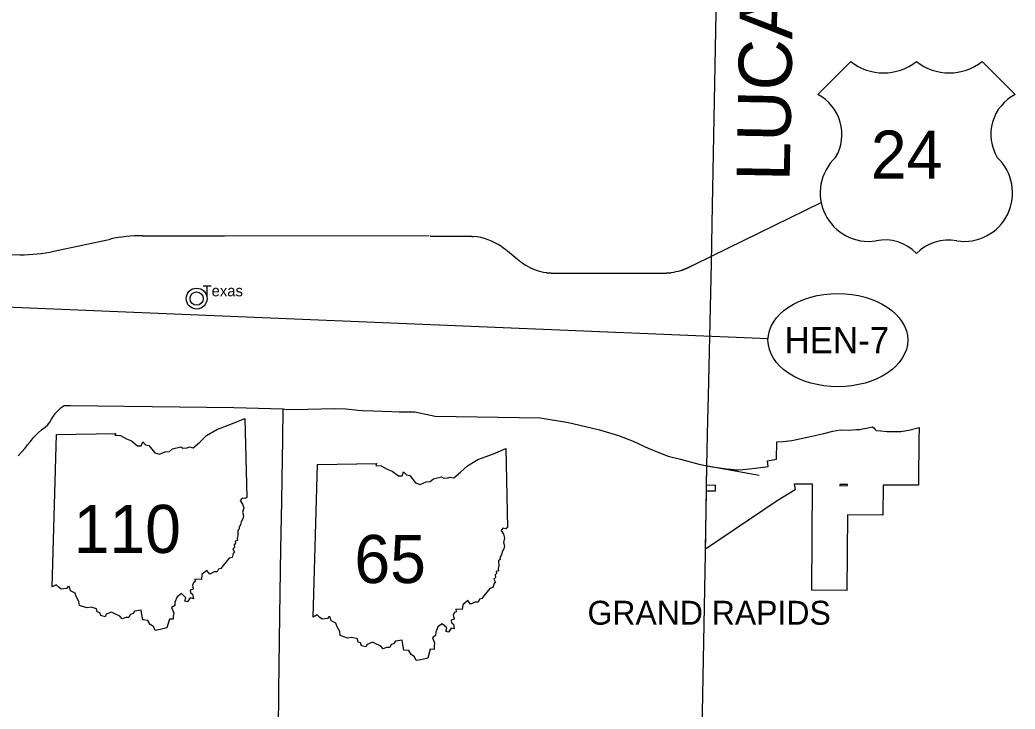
# Model space of a CAD drawing. Extents: x -62 to 810, y 0 to 440.
# Drawn here: x 408.1 to 514.9, y 275.7 to 349.6 of the extents above; entities that cross this region are included whole.
import ezdxf

# ---------------------------------------------------------------- set-up
doc = ezdxf.new("R2010")
doc.units = 0
for name, color, linetype in [('DV_X_Corp_Line', 7, 'Continuous'), ('GM_X_Adjacent_County_Text', 7, 'Continuous'), ('GM_X_Corporation_Text', 7, 'Continuous'), ('GM_X_County', 7, 'Continuous'), ('GM_X_State_Route', 7, 'Continuous'), ('PV_P_Text', 7, 'Continuous'), ('SH_Data', 7, 'Continuous')]:
    doc.layers.add(name, color=color, linetype=linetype)

msp = doc.modelspace()

# ---------------------------------------------------------------- linework, layer by layer
at = {"layer": 'DV_X_Corp_Line'}
for points in [[(481.71, 292.82), (481.82, 299.09), (482.78, 299.07), (482.78, 299.68), (481.83, 299.66), (481.87, 301.77), (482.48, 301.68), (483.97, 301.46), (484.43, 301.4), (484.71, 301.36), (484.94, 301.34), (485.26, 301.34), (485.71, 301.37), (486.42, 301.45), (487.03, 301.52), (488.18, 301.65), (488.45, 301.69), (488.38, 302.29), (489.35, 302.47), (489.37, 304.34), (490.04, 304.39), (490.97, 304.5), (492.79, 304.87), (494.42, 305.24), (495.37, 305.5), (496.18, 305.62), (497.09, 305.61), (497.93, 305.68), (498.27, 305.68), (498.57, 305.75), (498.98, 305.8), (499.6, 305.97), (499.78, 305.85), (499.89, 305.69), (500.03, 305.57), (500.53, 305.51), (501.2, 305.46), (502.03, 305.47), (502.68, 305.44), (503.53, 305.61), (504.63, 305.9), (504.61, 304.59), (504.56, 300.14), (504.56, 299.68), (500.79, 299.69), (500.73, 296.48), (496.94, 296.51), (496.87, 288.38), (493.14, 288.44), (493.2, 299.82), (491.74, 299.81), (491.23, 299.8), (491.3, 299.44), (491.34, 299.19), (489.39, 298.01)], [(496.14, 299.77), (496.14, 299.63), (496.97, 299.65), (496.97, 299.78)]]:
    msp.add_lwpolyline(points, close=True, dxfattribs=at)
for radius in [1.12, 0.71]:
    msp.add_circle((427.1, 319.72), radius, dxfattribs=at)
at = {"layer": 'GM_X_County'}
msp.add_lwpolyline([(480.48, 186.82), (480.48, 201.49), (480.48, 201.72), (480.54, 216.9), (480.6, 231.89), (480.65, 234.56), (480.88, 246.96), (481.15, 262.15), (481.29, 269.58), (481.42, 277.21), (481.7, 292.34), (481.87, 301.77), (481.96, 306.7), (482.02, 309.24), (482.36, 323.53), (482.48, 329.73), (482.51, 331.51), (482.76, 344.73), (482.9, 352.28)], dxfattribs=at)
at = {"layer": 'GM_X_State_Route'}
for p, q in [((482.43, 324.31), (494.13, 330.02)), ((414.8, 325.45), (417.84, 326.1)), ((421.27, 326.47), (428.1, 326.47)), ((428.1, 326.47), (430.08, 326.47)), ((430.08, 326.47), (452.06, 326.48)), ((411.78, 324.8), (414.8, 325.45)), ((403.76, 324.49), (408.13, 324.43)), ((460.85, 324.51), (461.28, 324.16)), ((480.39, 323.31), (482.43, 324.31)), ((466.02, 322.45), (476.64, 322.45)), ((452.7, 307.09), (463.96, 306.91))]:
    msp.add_line(p, q, dxfattribs=at)
for points in [[(411.22, 306.28), (411.35, 306.45), (411.53, 306.77), (411.75, 307.1), (411.96, 307.42), (412.55, 308.02), (412.87, 308.24), (413.02, 308.25), (413.28, 308.23), (413.58, 308.23), (431.09, 308.03)], [(431.09, 308.03), (436.4, 307.87)], [(435.86, 271.19), (435.89, 273.28), (435.94, 277.66), (436.03, 285.69), (436.15, 292.88), (436.23, 297.93), (436.28, 300.39), (436.36, 304.58), (436.4, 307.87)], [(436.4, 307.87), (436.73, 307.8), (438.99, 307.85), (441.94, 307.91), (443.13, 307.89), (444.43, 307.76), (444.91, 307.7), (446.05, 307.68), (448.05, 307.6), (448.83, 307.57), (450.53, 307.56), (452.7, 307.09)], [(463.96, 306.91), (466.79, 306.44), (467.47, 306.32), (470.32, 305.65), (472.39, 305.03), (473.96, 304.41), (475.64, 303.63), (477.71, 302.82), (479.03, 302.47), (481.14, 301.9), (487.46, 300.77)], [(407.94, 302.85), (408.34, 303.27), (408.69, 303.66), (408.95, 304.03), (409.23, 304.34), (409.62, 304.84), (409.87, 305.11), (410.1, 305.32), (410.46, 305.62), (410.85, 305.92), (411.12, 306.16), (411.2, 306.27), (411.22, 306.28)]]:
    msp.add_lwpolyline(points, dxfattribs=at)
for centre, radius, start, end in [((421.28, 310.14), 16.33, 90.0111, 102.1667), ((456.17, 319.89), 6.53, 56.1951, 84.2361), ((408.34, 340.76), 16.33, 269.2957, 282.1667), ((465.31, 327.91), 5.44, 237.9201, 262.5), ((477.35, 327.91), 5.44, 277.5, 288.5)]:
    msp.add_arc(centre, radius, start, end, dxfattribs=at)
for points in [[(452.17, 326.43), (455.51, 326.43), (455.53, 326.43), (455.55, 326.43), (455.57, 326.43), (455.58, 326.43), (455.6, 326.43), (455.62, 326.43), (455.64, 326.43), (455.66, 326.43), (455.67, 326.43), (455.69, 326.43), (455.71, 326.43), (455.73, 326.43), (455.74, 326.43), (455.76, 326.43), (455.78, 326.43), (455.8, 326.43), (455.82, 326.43), (455.83, 326.43), (455.85, 326.43), (455.87, 326.43), (455.89, 326.43), (455.9, 326.43), (455.92, 326.43), (455.94, 326.43), (455.96, 326.43), (455.98, 326.43), (455.99, 326.43), (456.01, 326.43), (456.03, 326.43), (456.05, 326.43), (456.07, 326.43), (456.08, 326.43), (456.1, 326.43), (456.12, 326.43), (456.14, 326.43), (456.15, 326.43), (456.17, 326.43), (456.19, 326.42), (456.21, 326.42), (456.23, 326.42), (456.24, 326.42), (456.26, 326.42), (456.28, 326.42), (456.3, 326.42), (456.31, 326.42), (456.33, 326.42), (456.35, 326.42), (456.37, 326.42), (456.39, 326.42), (456.4, 326.42), (456.42, 326.42), (456.44, 326.42), (456.46, 326.41), (456.47, 326.41), (456.49, 326.41), (456.51, 326.41), (456.53, 326.41), (456.55, 326.41), (456.56, 326.41), (456.58, 326.41), (456.6, 326.41), (456.62, 326.4), (456.63, 326.4), (456.65, 326.4), (456.67, 326.4), (456.69, 326.4), (456.7, 326.4), (456.72, 326.4), (456.74, 326.4), (456.76, 326.39), (456.78, 326.39), (456.79, 326.39), (456.81, 326.39), (456.83, 326.39)], [(459.81, 325.32), (459.82, 325.31), (459.84, 325.3), (459.85, 325.29), (459.87, 325.28), (459.88, 325.27), (459.9, 325.26), (459.91, 325.25), (459.92, 325.24), (459.94, 325.22), (459.95, 325.21), (459.97, 325.2), (459.98, 325.19), (460, 325.18), (460.01, 325.17), (460.03, 325.16), (460.04, 325.15), (460.05, 325.14), (460.07, 325.13), (460.08, 325.12), (460.1, 325.11), (460.11, 325.1), (460.13, 325.09), (460.14, 325.08), (460.15, 325.07), (460.17, 325.06), (460.18, 325.05), (460.2, 325.04), (460.21, 325.02), (460.23, 325.01), (460.24, 325), (460.25, 324.99), (460.27, 324.98), (460.28, 324.97), (460.3, 324.96), (460.31, 324.95), (460.32, 324.94), (460.34, 324.93), (460.35, 324.92), (460.37, 324.9), (460.38, 324.89), (460.39, 324.88), (460.41, 324.87), (460.42, 324.86), (460.44, 324.85), (460.45, 324.84), (460.46, 324.83), (460.48, 324.82), (460.49, 324.8), (460.5, 324.79), (460.52, 324.78), (460.53, 324.77), (460.55, 324.76), (460.56, 324.75), (460.57, 324.74), (460.59, 324.73), (460.6, 324.72), (460.62, 324.7), (460.63, 324.69), (460.64, 324.68), (460.66, 324.67), (460.67, 324.66), (460.68, 324.65), (460.7, 324.64), (460.71, 324.62), (460.73, 324.61), (460.74, 324.6), (460.75, 324.59), (460.77, 324.58), (460.78, 324.57), (460.79, 324.56), (460.81, 324.55), (460.82, 324.53), (460.84, 324.52), (460.85, 324.51)], [(461.28, 324.16), (461.29, 324.14), (461.31, 324.13), (461.32, 324.12), (461.34, 324.11), (461.35, 324.09), (461.37, 324.08), (461.38, 324.07), (461.4, 324.06), (461.41, 324.05), (461.43, 324.03), (461.44, 324.02), (461.46, 324.01), (461.47, 324), (461.49, 323.98), (461.5, 323.97), (461.52, 323.96), (461.53, 323.95), (461.55, 323.94), (461.56, 323.92), (461.58, 323.91), (461.59, 323.9), (461.61, 323.89), (461.62, 323.87), (461.64, 323.86), (461.65, 323.85), (461.67, 323.84), (461.68, 323.83), (461.7, 323.81), (461.71, 323.8), (461.73, 323.79), (461.74, 323.78), (461.76, 323.77), (461.77, 323.75), (461.79, 323.74), (461.8, 323.73), (461.82, 323.72), (461.83, 323.71), (461.85, 323.7), (461.86, 323.68), (461.88, 323.67), (461.89, 323.66), (461.91, 323.65), (461.93, 323.64), (461.94, 323.63), (461.96, 323.61), (461.97, 323.6), (461.99, 323.59), (462, 323.58), (462.02, 323.57), (462.03, 323.56), (462.05, 323.55), (462.06, 323.53), (462.08, 323.52), (462.1, 323.51), (462.11, 323.5), (462.13, 323.49), (462.14, 323.48), (462.16, 323.47), (462.17, 323.46), (462.19, 323.45), (462.21, 323.43), (462.22, 323.42), (462.24, 323.41), (462.25, 323.4), (462.27, 323.39), (462.29, 323.38), (462.3, 323.37), (462.32, 323.36), (462.33, 323.35), (462.35, 323.34), (462.37, 323.33), (462.38, 323.32), (462.4, 323.31), (462.42, 323.3)], [(479.08, 322.75), (479.1, 322.75), (479.12, 322.76), (479.14, 322.77), (479.15, 322.77), (479.17, 322.78), (479.19, 322.78), (479.21, 322.79), (479.23, 322.8), (479.24, 322.8), (479.26, 322.81), (479.28, 322.82), (479.3, 322.82), (479.32, 322.83), (479.33, 322.84), (479.35, 322.85), (479.37, 322.85), (479.39, 322.86), (479.41, 322.87), (479.42, 322.87), (479.44, 322.88), (479.46, 322.89), (479.48, 322.9), (479.5, 322.9), (479.51, 322.91), (479.53, 322.92), (479.55, 322.93), (479.57, 322.93), (479.58, 322.94), (479.6, 322.95), (479.62, 322.96), (479.64, 322.96), (479.65, 322.97), (479.67, 322.98), (479.69, 322.99), (479.71, 322.99), (479.73, 323), (479.74, 323.01), (479.76, 323.02), (479.78, 323.03), (479.8, 323.03), (479.81, 323.04), (479.83, 323.05), (479.85, 323.06), (479.87, 323.07), (479.88, 323.07), (479.9, 323.08), (479.92, 323.09), (479.94, 323.1), (479.95, 323.11), (479.97, 323.11), (479.99, 323.12), (480.01, 323.13), (480.02, 323.14), (480.04, 323.15), (480.06, 323.16), (480.07, 323.16), (480.09, 323.17), (480.11, 323.18), (480.13, 323.19), (480.14, 323.2), (480.16, 323.21), (480.18, 323.21), (480.2, 323.22), (480.21, 323.23), (480.23, 323.24), (480.25, 323.25), (480.27, 323.26), (480.28, 323.26), (480.3, 323.27), (480.32, 323.28), (480.33, 323.29), (480.35, 323.3), (480.37, 323.31), (480.39, 323.31)], [(464.6, 322.51), (464.61, 322.51), (464.63, 322.51), (464.65, 322.51), (464.67, 322.5), (464.69, 322.5), (464.71, 322.5), (464.73, 322.5), (464.75, 322.49), (464.77, 322.49), (464.79, 322.49), (464.81, 322.49), (464.83, 322.49), (464.84, 322.49), (464.86, 322.48), (464.88, 322.48), (464.9, 322.48), (464.92, 322.48), (464.94, 322.48), (464.96, 322.48), (464.98, 322.47), (465, 322.47), (465.02, 322.47), (465.04, 322.47), (465.06, 322.47), (465.08, 322.47), (465.09, 322.47), (465.11, 322.47), (465.13, 322.47), (465.15, 322.46), (465.17, 322.46), (465.19, 322.46), (465.21, 322.46), (465.23, 322.46), (465.25, 322.46), (465.27, 322.46), (465.29, 322.46), (465.31, 322.46), (465.33, 322.46), (465.34, 322.46), (465.36, 322.46), (465.38, 322.46), (465.4, 322.46), (465.42, 322.45), (465.44, 322.45), (465.46, 322.45), (465.48, 322.45), (465.5, 322.45), (465.52, 322.45), (465.54, 322.45), (465.56, 322.45), (465.58, 322.45), (465.59, 322.45), (465.61, 322.45), (465.63, 322.45), (465.65, 322.45), (465.67, 322.45), (465.69, 322.45), (465.71, 322.45), (465.73, 322.45), (465.75, 322.45), (465.77, 322.45), (465.79, 322.45), (465.81, 322.45), (465.83, 322.45), (465.84, 322.45), (465.86, 322.45), (465.88, 322.45), (465.9, 322.45), (465.92, 322.45), (465.94, 322.45), (465.96, 322.45), (465.98, 322.45), (466, 322.45), (466.02, 322.45)], [(476.64, 322.45), (476.66, 322.45), (476.68, 322.45), (476.7, 322.45), (476.72, 322.45), (476.74, 322.45), (476.76, 322.45), (476.78, 322.45), (476.8, 322.45), (476.81, 322.45), (476.83, 322.45), (476.85, 322.45), (476.87, 322.45), (476.89, 322.45), (476.91, 322.45), (476.93, 322.45), (476.95, 322.45), (476.97, 322.45), (476.99, 322.45), (477.01, 322.45), (477.03, 322.45), (477.05, 322.45), (477.07, 322.45), (477.08, 322.45), (477.1, 322.45), (477.12, 322.45), (477.14, 322.45), (477.16, 322.45), (477.18, 322.45), (477.2, 322.45), (477.22, 322.45), (477.24, 322.45), (477.26, 322.46), (477.28, 322.46), (477.3, 322.46), (477.32, 322.46), (477.33, 322.46), (477.35, 322.46), (477.37, 322.46), (477.39, 322.46), (477.41, 322.46), (477.43, 322.46), (477.45, 322.46), (477.47, 322.46), (477.49, 322.46), (477.51, 322.46), (477.53, 322.47), (477.55, 322.47), (477.57, 322.47), (477.58, 322.47), (477.6, 322.47), (477.62, 322.47), (477.64, 322.47), (477.66, 322.47), (477.68, 322.47), (477.7, 322.48), (477.72, 322.48), (477.74, 322.48), (477.76, 322.48), (477.78, 322.48), (477.8, 322.48), (477.82, 322.49), (477.83, 322.49), (477.85, 322.49), (477.87, 322.49), (477.89, 322.49), (477.91, 322.49), (477.93, 322.5), (477.95, 322.5), (477.97, 322.5), (477.99, 322.5), (478.01, 322.51), (478.03, 322.51), (478.04, 322.51), (478.06, 322.51)]]:
    msp.add_spline(points, degree=3, dxfattribs=at)
at = {"layer": 'PV_P_Text'}
for p, q in [((497.3, 345.17), (493.76, 341.62)), ((514.94, 341.62), (511.39, 345.17)), ((411.61, 288.77), (412.07, 305.14)), ((411.61, 288.77), (412.07, 305.14)), ((439.61, 285.54), (440.07, 301.91)), ((439.61, 285.54), (440.07, 301.91))]:
    msp.add_line(p, q, dxfattribs=at)
for points in [[(412.07, 305.14), (418.42, 305.25), (418.32, 305.05), (418.92, 305.01), (419.56, 304.66), (420.1, 304.44), (420.76, 303.92), (421.15, 303.92), (421.32, 304.35), (421.62, 304.02), (421.98, 303.96), (422.6, 303.18), (423.11, 303.01), (423.72, 303.27), (424.18, 303.32), (424.51, 303.58), (425.39, 303.81), (425.63, 303.68), (426.09, 303.7), (426.32, 303.8), (426.72, 303.71), (427.43, 304.31), (428.16, 305.01), (429.28, 305.67), (430.96, 306.3), (432.29, 306.86), (432.48, 298.36)], [(412.07, 305.14), (418.42, 305.25), (418.32, 305.05), (418.92, 305.01), (419.56, 304.66), (420.1, 304.44), (420.76, 303.92), (421.15, 303.92), (421.32, 304.35), (421.62, 304.02), (421.98, 303.96), (422.6, 303.18), (423.11, 303.01), (423.72, 303.27), (424.18, 303.32), (424.51, 303.58), (425.39, 303.81), (425.63, 303.68), (426.09, 303.7), (426.32, 303.8), (426.72, 303.71), (427.43, 304.31), (428.16, 305.01), (429.28, 305.67), (430.96, 306.3), (432.29, 306.86), (432.48, 298.36)], [(440.07, 301.91), (446.42, 302.02), (446.32, 301.82), (446.92, 301.78), (447.56, 301.43), (448.09, 301.21), (448.75, 300.69), (449.15, 300.69), (449.31, 301.12), (449.62, 300.79), (449.97, 300.73), (450.59, 299.95), (451.1, 299.78), (451.72, 300.05), (452.17, 300.09), (452.51, 300.36), (453.38, 300.58), (453.62, 300.45), (454.09, 300.47), (454.32, 300.57), (454.72, 300.48), (455.43, 301.08), (456.16, 301.78), (457.28, 302.44), (458.96, 303.07), (460.28, 303.63), (460.47, 295.14)], [(440.07, 301.91), (446.42, 302.02), (446.32, 301.82), (446.92, 301.78), (447.56, 301.43), (448.09, 301.21), (448.75, 300.69), (449.15, 300.69), (449.31, 301.12), (449.62, 300.79), (449.97, 300.73), (450.59, 299.95), (451.1, 299.78), (451.72, 300.05), (452.17, 300.09), (452.51, 300.36), (453.38, 300.58), (453.62, 300.45), (454.09, 300.47), (454.32, 300.57), (454.72, 300.48), (455.43, 301.08), (456.16, 301.78), (457.28, 302.44), (458.96, 303.07), (460.28, 303.63), (460.47, 295.14)], [(432.48, 298.36), (432.28, 298.25), (431.98, 298.3), (431.77, 298.06), (432.03, 297.67), (432.15, 297.25), (432.04, 296.78), (432.14, 296.4), (432.07, 296.08), (431.88, 295.76), (431.82, 295.46), (431.65, 295.14), (431.67, 294.96), (431.51, 294.82), (431.54, 294.29), (431.46, 293.99), (431.49, 293.74), (431.24, 293.67), (431.29, 293.46), (431.13, 293.3), (431.17, 293.02), (430.99, 292.84), (431.16, 292.49), (431.02, 292.37), (430.9, 291.94), (430.58, 291.85), (429.94, 291.06), (429.71, 290.76), (429.45, 290.69), (429.31, 290.38), (428.99, 290.38), (428.52, 290.16), (428.21, 290.53), (427.67, 290.09), (427.61, 289.58), (426.92, 289.59), (426.95, 289.34), (426.8, 289.26), (426.66, 289), (426.74, 288.54), (426.42, 288.43), (426.46, 288.16), (426.66, 288), (426.75, 287.49), (426.41, 287.59), (426.13, 287.16), (425.85, 287.26), (425.94, 287.62), (425.46, 288.06), (425, 287.71), (424.76, 287.15), (424.76, 286.77), (424.42, 286.55), (424.64, 286.01), (424.6, 285.65), (424.6, 285.3), (424.18, 285.31), (423.92, 284.37)], [(432.48, 298.36), (432.28, 298.25), (431.98, 298.3), (431.77, 298.06), (432.03, 297.67), (432.15, 297.25), (432.04, 296.78), (432.14, 296.4), (432.07, 296.08), (431.88, 295.76), (431.82, 295.46), (431.65, 295.14), (431.67, 294.96), (431.51, 294.82), (431.54, 294.29), (431.46, 293.99), (431.49, 293.74), (431.24, 293.67), (431.29, 293.46), (431.13, 293.3), (431.17, 293.02), (430.99, 292.84), (431.16, 292.49), (431.02, 292.37), (430.9, 291.94), (430.58, 291.85), (429.94, 291.06), (429.71, 290.76), (429.45, 290.69), (429.31, 290.38), (428.99, 290.38), (428.52, 290.16), (428.21, 290.53), (427.67, 290.09), (427.61, 289.58), (426.92, 289.59), (426.95, 289.34), (426.8, 289.26), (426.66, 289), (426.74, 288.54), (426.42, 288.43), (426.46, 288.16), (426.66, 288), (426.75, 287.49), (426.41, 287.59), (426.13, 287.16), (425.85, 287.26), (425.94, 287.62), (425.46, 288.06), (425, 287.71), (424.76, 287.15), (424.76, 286.77), (424.42, 286.55), (424.64, 286.01), (424.6, 285.65), (424.6, 285.3), (424.18, 285.31), (423.92, 284.37)], [(460.47, 295.14), (460.28, 295.02), (459.97, 295.07), (459.77, 294.83), (460.02, 294.44), (460.14, 294.02), (460.04, 293.55), (460.14, 293.17), (460.07, 292.85), (459.88, 292.53), (459.81, 292.23), (459.65, 291.91), (459.66, 291.73), (459.51, 291.59), (459.53, 291.06), (459.46, 290.76), (459.48, 290.51), (459.23, 290.44), (459.29, 290.23), (459.13, 290.07), (459.16, 289.79), (458.98, 289.62), (459.16, 289.26), (459.02, 289.15), (458.9, 288.71), (458.58, 288.62), (457.93, 287.83), (457.7, 287.53), (457.45, 287.46), (457.31, 287.15), (456.99, 287.15), (456.51, 286.93), (456.2, 287.3), (455.66, 286.86), (455.6, 286.35), (454.92, 286.37), (454.95, 286.11), (454.79, 286.03), (454.65, 285.77), (454.73, 285.31), (454.41, 285.2), (454.45, 284.93), (454.66, 284.77), (454.75, 284.26), (454.41, 284.36), (454.13, 283.93), (453.84, 284.03), (453.94, 284.4), (453.45, 284.83), (453, 284.48), (452.76, 283.92), (452.75, 283.55), (452.41, 283.32), (452.63, 282.79), (452.59, 282.42), (452.6, 282.07), (452.17, 282.08), (451.91, 281.14)], [(460.47, 295.14), (460.28, 295.02), (459.97, 295.07), (459.77, 294.83), (460.02, 294.44), (460.14, 294.02), (460.04, 293.55), (460.14, 293.17), (460.07, 292.85), (459.88, 292.53), (459.81, 292.23), (459.65, 291.91), (459.66, 291.73), (459.51, 291.59), (459.53, 291.06), (459.46, 290.76), (459.48, 290.51), (459.23, 290.44), (459.29, 290.23), (459.13, 290.07), (459.16, 289.79), (458.98, 289.62), (459.16, 289.26), (459.02, 289.15), (458.9, 288.71), (458.58, 288.62), (457.93, 287.83), (457.7, 287.53), (457.45, 287.46), (457.31, 287.15), (456.99, 287.15), (456.51, 286.93), (456.2, 287.3), (455.66, 286.86), (455.6, 286.35), (454.92, 286.37), (454.95, 286.11), (454.79, 286.03), (454.65, 285.77), (454.73, 285.31), (454.41, 285.2), (454.45, 284.93), (454.66, 284.77), (454.75, 284.26), (454.41, 284.36), (454.13, 283.93), (453.84, 284.03), (453.94, 284.4), (453.45, 284.83), (453, 284.48), (452.76, 283.92), (452.75, 283.55), (452.41, 283.32), (452.63, 282.79), (452.59, 282.42), (452.6, 282.07), (452.17, 282.08), (451.91, 281.14)], [(423.92, 284.37), (423.18, 284.19), (422.66, 284.08), (422.48, 284.51), (422.11, 284.74), (421.87, 285.17), (421.34, 285.23), (421.22, 285.82), (421.16, 286.29), (420.44, 286.18), (420.24, 285.88), (419.98, 285.8), (419.83, 285.51), (419.49, 285.48), (419.11, 285.35), (418.87, 285.64), (418.25, 285.93), (417.98, 286.08), (417.4, 285.84), (417.27, 285.57), (416.81, 285.69), (416.71, 286), (416.43, 286.09), (416.37, 286.41), (415.77, 286.59), (415.32, 286.52), (414.52, 286.78), (414.47, 287.21), (414.19, 287.73), (414.05, 288.1), (413.55, 288.37), (413.44, 288.81), (413.28, 288.79), (413.13, 288.62), (412.57, 288.54), (412.34, 288.71), (412.03, 289.01), (411.61, 288.77)], [(423.92, 284.37), (423.18, 284.19), (422.66, 284.08), (422.48, 284.51), (422.11, 284.74), (421.87, 285.17), (421.34, 285.23), (421.22, 285.82), (421.16, 286.29), (420.44, 286.18), (420.24, 285.88), (419.98, 285.8), (419.83, 285.51), (419.49, 285.48), (419.11, 285.35), (418.87, 285.64), (418.25, 285.93), (417.98, 286.08), (417.4, 285.84), (417.27, 285.57), (416.81, 285.69), (416.71, 286), (416.43, 286.09), (416.37, 286.41), (415.77, 286.59), (415.32, 286.52), (414.52, 286.78), (414.47, 287.21), (414.19, 287.73), (414.05, 288.1), (413.55, 288.37), (413.44, 288.81), (413.28, 288.79), (413.13, 288.62), (412.57, 288.54), (412.34, 288.71), (412.03, 289.01), (411.61, 288.77)], [(451.91, 281.14), (451.17, 280.96), (450.66, 280.86), (450.48, 281.28), (450.11, 281.51), (449.87, 281.94), (449.34, 282), (449.22, 282.59), (449.16, 283.07), (448.43, 282.95), (448.24, 282.65), (447.98, 282.58), (447.83, 282.28), (447.48, 282.26), (447.11, 282.12), (446.86, 282.41), (446.25, 282.7), (445.97, 282.85), (445.39, 282.61), (445.27, 282.34), (444.81, 282.46), (444.7, 282.77), (444.42, 282.86), (444.36, 283.19), (443.77, 283.36), (443.31, 283.29), (442.51, 283.55), (442.46, 283.98), (442.19, 284.5), (442.05, 284.87), (441.54, 285.14), (441.44, 285.58), (441.28, 285.56), (441.13, 285.39), (440.56, 285.31), (440.34, 285.48), (440.02, 285.79), (439.61, 285.54)], [(451.91, 281.14), (451.17, 280.96), (450.66, 280.86), (450.48, 281.28), (450.11, 281.51), (449.87, 281.94), (449.34, 282), (449.22, 282.59), (449.16, 283.07), (448.43, 282.95), (448.24, 282.65), (447.98, 282.58), (447.83, 282.28), (447.48, 282.26), (447.11, 282.12), (446.86, 282.41), (446.25, 282.7), (445.97, 282.85), (445.39, 282.61), (445.27, 282.34), (444.81, 282.46), (444.7, 282.77), (444.42, 282.86), (444.36, 283.19), (443.77, 283.36), (443.31, 283.29), (442.51, 283.55), (442.46, 283.98), (442.19, 284.5), (442.05, 284.87), (441.54, 285.14), (441.44, 285.58), (441.28, 285.56), (441.13, 285.39), (440.56, 285.31), (440.34, 285.48), (440.02, 285.79), (439.61, 285.54)]]:
    msp.add_lwpolyline(points, dxfattribs=at)
for centre, radius, start, end in [((500.82, 349.64), 5.7, 231.813, 308.187), ((507.87, 349.64), 5.7, 231.813, 308.187), ((491.54, 337.34), 4.82, 329.1175, 62.6108), ((517.16, 337.34), 4.82, 117.3892, 210.8825), ((499.22, 331.06), 5.2, 133.0046, 278.7282), ((509.47, 331.06), 5.2, 261.2718, 46.9954), ((500.97, 321.37), 4.65, 43.4177, 101.8742), ((507.82, 321.06), 4.94, 79.9613, 134.7468)]:
    msp.add_arc(centre, radius, start, end, dxfattribs=at)
at = {"layer": 'SH_Data'}
msp.add_line((488.43, 315.4), (383.92, 319.74), dxfattribs=at)
msp.add_ellipse((495.92, 315.26), major_axis=(7.5, 0), ratio=0.666667, dxfattribs=at)

# ---------------------------------------------------------------- texts
at = {"layer": 'GM_X_Adjacent_County_Text'}
msp.add_text('LUCAS COUNTY', height=5.7, rotation=88.9277, dxfattribs=at).set_placement((490.74, 332.27))
at = {"layer": 'GM_X_Corporation_Text'}
for s, height, p in [('Texas', 1.188, (427.74, 319.96)), ('GRAND RAPIDS', 2.565, (469.05, 284.72))]:
    msp.add_text(s, height=height, rotation=0, dxfattribs=at).set_placement(p)
at = {"layer": 'PV_P_Text'}
for s, p in [('24', (499.46, 332.59)), ('110', (413.9, 292.42)), ('65', (444.03, 289.19))]:
    msp.add_text(s, height=5.162, dxfattribs=at).set_placement(p)
at = {"layer": 'SH_Data'}
msp.add_text('HEN-7', height=2.8, dxfattribs=at).set_placement((490.19, 313.86))

doc.saveas('drawing.dxf')
